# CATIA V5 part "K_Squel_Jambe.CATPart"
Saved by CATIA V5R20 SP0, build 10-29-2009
Part number: Squelette_structure
Publications: "Droite.4", "Plan.4", "Point.2", "Point.4", "Plan.5", "Point.3", "Longueur_structure", "entraxe_struct_balancier", "entraxe_struct_bras", "Plan.8", "Plan_demi_longueur_2"
Bounding box of the stored display mesh (mm): x -87 to 87, y -106.066 to 106.066, z -106.066 to 106.066
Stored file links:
  G:\Khaled_CFAO_2011\ST2M\ST2M_GR2\plakomicki\Khaled\CAD_ThinkMOTION\K_Squel_Jambe.CATPart
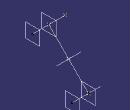
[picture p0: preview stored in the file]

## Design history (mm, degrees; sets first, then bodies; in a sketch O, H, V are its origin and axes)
Parameters
  Longueur_structure = 300 mm
  entraxe_struct_bras = 87 mm
  entraxe_struct_balancier = 38 mm
Set1
  Point1: (0, 0, 0)
  Line1 "axe_rotation_plan_ref_struct": type PtDir, RefPoint Point1, Direction yz-plane, Start 0, End 5
  Plane1 "Plan_ref_struct": type Angle, RefPlane zx-plane, Direction Line1, Angle -45
  Plane2 "Plan_demi_longueur_1": type Offset, RefPlane Plane1, Offset 150 {= Longueur_structure /2}
  Plane3 "Plan_demi_longueur_2": type Offset, RefPlane Plane1, Offset -150 {= -Longueur_structure/2}
  Point2 "Point_struct_bras": type OnPlane, Support Plane3, H 0, V 0, Direction (-1, 0, 0)
  Point3 "Point_struct_balancier": type OnPlane, Support Plane2, H 0, V 0, Direction (-1, 0, 0)
  Line2 "longueur_struct": type PtPt, FirstPoint Point2, SecondPoint Point3
  Plane4 "Plan_pivot_struct_bras": type OffsetPt, RefPlane yz-plane, RefPoint Point2
  Plane5: type OffsetPt, RefPlane yz-plane, RefPoint Point3
  Line3 "axe_pivot_struct_bras": type PtDir, RefPoint Point2, Direction Plane4, Start 87 {= entraxe_struct_bras}, End -87
  Line4 "axe_pivot_struct_balancier": type PtDir, RefPoint Point3, Direction Plane5, Start -87, End 0
  Point4: type OnCurve, Support Line3, Length 0
  Plane6 "Plan_pivot_struct_balancier": type OffsetPt, RefPlane yz-plane, RefPoint vertex of Line4
  Plane7: type OffsetPt, RefPlane Plane4, RefPoint vertex of Line3
Body1 (main body)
